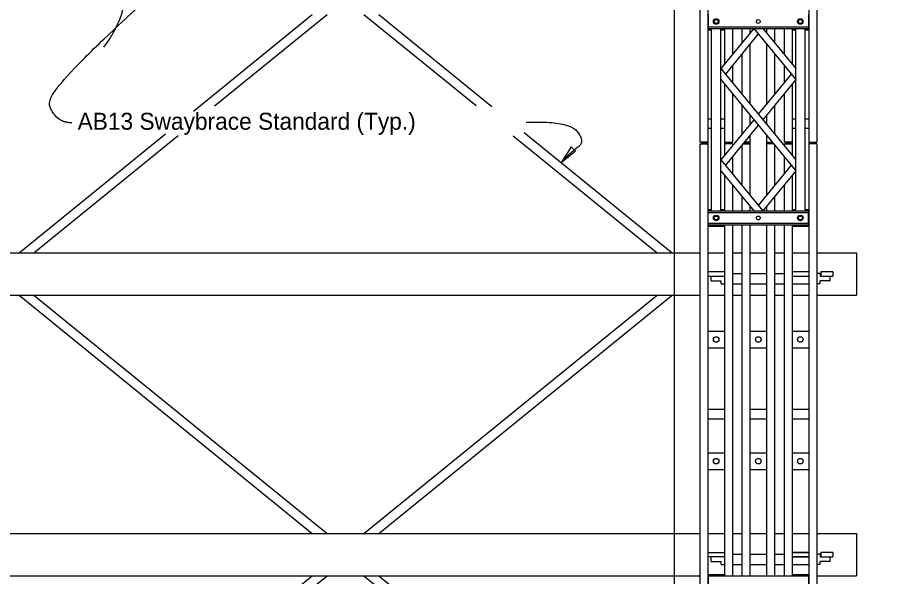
# Model space of a CAD drawing. Extents: x 10618 to 10724, y 76431 to 76484.
# Drawn here: x 10649.06 to 10664.57, y 76454.3 to 76464.26 of the extents above; entities that cross this region are included whole.
import ezdxf

# ---------------------------------------------------------------- set-up
doc = ezdxf.new("R2010")
doc.units = 0
for name, color, linetype in [('Dimension', 7, 'Continuous'), ('GroundLines', 7, 'Continuous'), ('SteelMisc', 7, 'Continuous'), ('SteelMisc_h', 7, 'Continuous'), ('TextStructures', 7, 'Continuous')]:
    doc.layers.add(name, color=color, linetype=linetype)

msp = doc.modelspace()

# ---------------------------------------------------------------- linework, layer by layer
at = {"layer": 'Dimension'}
msp.add_lwpolyline([(10658.757, 76461.681), (10659.005, 76461.878), (10658.927, 76461.949)], close=True, dxfattribs=at)
for points in [[(10650.607, 76463.726), (10650.975, 76464.246), (10650.975, 76465.012), (10650.65, 76466.059)], [(10650.033, 76462.379), (10649.734, 76462.379), (10649.531, 76463.039), (10653.036, 76466.033)], [(10658.129, 76462.389), (10658.88, 76462.418), (10659.189, 76462.04), (10658.9, 76461.84), (10658.757, 76461.681)]]:
    msp.add_open_spline(points, degree=2, dxfattribs=at)
at = {"layer": 'GroundLines'}
msp.add_arc((10662.764, 76474.227), 22, 271.4107, 319.8102, dxfattribs=at)
at = {"layer": 'SteelMisc'}
for p, q in [((10660.764, 76474.685), (10660.764, 76448.199)), ((10661.365, 76472.269), (10661.365, 76452.037)), ((10663.162, 76472.269), (10663.162, 76452.037)), ((10661.222, 76471.998), (10661.222, 76462.037)), ((10663.305, 76471.998), (10663.305, 76462.037)), ((10661.368, 76464.31), (10661.368, 76464.06)), ((10663.159, 76464.31), (10663.159, 76464.06)), ((10661.368, 76464.091), (10663.159, 76464.091)), ((10661.368, 76464.06), (10663.159, 76464.06)), ((10661.43, 76460.81), (10661.43, 76464.06)), ((10661.597, 76460.81), (10661.597, 76464.06)), ((10662.183, 76464.06), (10661.597, 76463.346)), ((10661.662, 76464.06), (10661.662, 76463.425)), ((10661.805, 76464.06), (10661.805, 76463.6)), ((10661.972, 76464.06), (10661.972, 76463.803)), ((10662.115, 76464.06), (10662.115, 76463.978)), ((10662.183, 76464.06), (10662.93, 76463.149)), ((10662.344, 76464.06), (10662.93, 76463.346)), ((10662.412, 76464.06), (10662.412, 76463.978)), ((10662.555, 76464.06), (10662.555, 76463.803)), ((10662.722, 76464.06), (10662.722, 76463.6)), ((10662.865, 76464.06), (10662.865, 76463.425)), ((10662.93, 76460.81), (10662.93, 76464.06)), ((10663.097, 76460.81), (10663.097, 76464.06)), ((10661.365, 76464.037), (10661.43, 76464.037)), ((10661.597, 76464.037), (10661.662, 76464.037)), ((10662.263, 76463.962), (10661.678, 76463.248)), ((10662.865, 76464.037), (10662.93, 76464.037)), ((10663.097, 76464.037), (10663.162, 76464.037)), ((10662.115, 76463.781), (10662.115, 76462.714)), ((10662.412, 76463.781), (10662.412, 76462.715)), ((10661.972, 76463.606), (10661.972, 76462.889)), ((10662.555, 76463.606), (10662.555, 76462.889)), ((10661.597, 76463.346), (10662.93, 76461.721)), ((10661.805, 76463.403), (10661.805, 76463.092)), ((10662.722, 76463.403), (10662.722, 76463.093)), ((10661.597, 76463.149), (10662.93, 76461.524)), ((10662.849, 76463.248), (10662.263, 76462.534)), ((10662.93, 76463.149), (10662.344, 76462.435)), ((10661.662, 76463.07), (10661.662, 76461.8)), ((10662.865, 76463.07), (10662.865, 76461.8)), ((10661.805, 76462.895), (10661.805, 76462.037)), ((10662.722, 76462.896), (10662.722, 76462.037)), ((10661.972, 76462.692), (10661.972, 76462.178)), ((10662.555, 76462.692), (10662.555, 76462.178)), ((10662.115, 76462.517), (10662.115, 76462.353)), ((10662.412, 76462.518), (10662.412, 76462.353)), ((10661.43, 76462.446), (10661.365, 76462.446)), ((10661.662, 76462.446), (10661.597, 76462.446)), ((10662.183, 76462.435), (10661.597, 76461.721)), ((10662.263, 76462.337), (10661.678, 76461.623)), ((10662.93, 76462.446), (10662.865, 76462.446)), ((10663.162, 76462.446), (10663.097, 76462.446)), ((10661.43, 76462.279), (10661.365, 76462.279)), ((10661.365, 76462.269), (10661.365, 76448.199)), ((10661.662, 76462.279), (10661.597, 76462.279)), ((10662.93, 76462.279), (10662.865, 76462.279)), ((10663.162, 76462.279), (10663.097, 76462.279)), ((10663.162, 76462.269), (10663.162, 76448.199)), ((10661.365, 76462.037), (10661.222, 76462.037)), ((10661.365, 76462.037), (10661.222, 76462.037)), ((10661.255, 76462.037), (10661.255, 76462.019)), ((10661.338, 76462.037), (10661.338, 76462.019)), ((10661.662, 76462.037), (10661.805, 76462.037)), ((10661.662, 76462.037), (10661.805, 76462.037)), ((10661.688, 76462.037), (10661.688, 76462.019)), ((10661.772, 76462.037), (10661.772, 76462.019)), ((10662.115, 76462.037), (10662.017, 76462.037)), ((10662.088, 76462.037), (10662.088, 76462.019)), ((10662.115, 76462.156), (10662.115, 76461.089)), ((10662.412, 76462.156), (10662.412, 76461.09)), ((10662.412, 76462.037), (10662.51, 76462.037)), ((10662.438, 76462.037), (10662.438, 76462.019)), ((10662.865, 76462.037), (10662.722, 76462.037)), ((10662.865, 76462.037), (10662.722, 76462.037)), ((10662.755, 76462.037), (10662.755, 76462.019)), ((10662.838, 76462.037), (10662.838, 76462.019)), ((10663.162, 76462.037), (10663.305, 76462.037)), ((10663.162, 76462.037), (10663.305, 76462.037)), ((10663.188, 76462.037), (10663.188, 76462.019)), ((10663.272, 76462.037), (10663.272, 76462.019)), ((10661.222, 76462.002), (10661.222, 76452.037)), ((10661.222, 76462.002), (10661.365, 76462.002)), ((10661.338, 76462.019), (10661.255, 76462.019)), ((10661.805, 76462.002), (10661.662, 76462.002)), ((10661.688, 76462.019), (10661.772, 76462.019)), ((10661.805, 76462.002), (10661.805, 76461.975)), ((10661.972, 76461.981), (10661.972, 76461.264)), ((10661.989, 76462.002), (10662.115, 76462.002)), ((10662.005, 76462.022), (10662.005, 76462.019)), ((10662.088, 76462.019), (10662.005, 76462.019)), ((10662.538, 76462.002), (10662.412, 76462.002)), ((10662.438, 76462.019), (10662.522, 76462.019)), ((10662.522, 76462.022), (10662.522, 76462.019)), ((10662.555, 76461.981), (10662.555, 76461.264)), ((10662.722, 76462.002), (10662.722, 76461.975)), ((10662.722, 76462.002), (10662.865, 76462.002)), ((10662.838, 76462.019), (10662.755, 76462.019)), ((10663.305, 76462.002), (10663.162, 76462.002)), ((10663.188, 76462.019), (10663.272, 76462.019)), ((10663.305, 76462.002), (10663.305, 76452.037)), ((10661.597, 76461.721), (10662.344, 76460.81)), ((10661.805, 76461.778), (10661.805, 76461.467)), ((10662.722, 76461.778), (10662.722, 76461.468)), ((10662.849, 76461.623), (10662.263, 76460.909)), ((10661.597, 76461.524), (10662.183, 76460.81)), ((10661.662, 76461.445), (10661.662, 76460.81)), ((10662.93, 76461.524), (10662.344, 76460.81)), ((10662.865, 76461.445), (10662.865, 76460.81)), ((10661.805, 76461.27), (10661.805, 76460.81)), ((10662.722, 76461.271), (10662.722, 76460.81)), ((10661.972, 76461.067), (10661.972, 76460.81)), ((10662.555, 76461.067), (10662.555, 76460.81)), ((10661.365, 76460.834), (10661.43, 76460.834)), ((10661.368, 76460.81), (10663.159, 76460.81)), ((10661.368, 76460.56), (10661.368, 76460.81)), ((10661.597, 76460.834), (10661.662, 76460.834)), ((10662.115, 76460.892), (10662.115, 76460.81)), ((10662.412, 76460.893), (10662.412, 76460.81)), ((10662.865, 76460.834), (10662.93, 76460.834)), ((10663.097, 76460.834), (10663.162, 76460.834)), ((10663.159, 76460.56), (10663.159, 76460.81)), ((10661.368, 76460.78), (10663.159, 76460.78)), ((10661.365, 76460.537), (10661.662, 76460.537)), ((10661.368, 76460.591), (10663.159, 76460.591)), ((10661.368, 76460.56), (10663.159, 76460.56)), ((10661.662, 76460.56), (10661.662, 76454.31)), ((10661.805, 76460.56), (10661.805, 76454.311)), ((10661.972, 76460.56), (10661.972, 76454.311)), ((10662.115, 76460.56), (10662.115, 76454.311)), ((10662.412, 76460.56), (10662.412, 76454.31)), ((10662.555, 76460.56), (10662.555, 76454.311)), ((10662.722, 76460.56), (10662.722, 76454.311)), ((10662.865, 76460.56), (10662.865, 76454.31)), ((10662.865, 76460.537), (10663.162, 76460.537)), ((10661.365, 76460.061), (10661.662, 76460.061)), ((10661.805, 76460.061), (10661.972, 76460.061)), ((10662.115, 76460.061), (10662.412, 76460.061)), ((10662.555, 76460.061), (10662.722, 76460.061)), ((10662.865, 76460.061), (10663.162, 76460.061)), ((10663.305, 76460.061), (10664.014, 76460.061)), ((10664.014, 76460.061), (10664.014, 76459.311)), ((10661.662, 76459.726), (10661.365, 76459.726)), ((10663.162, 76459.726), (10662.865, 76459.726)), ((10663.162, 76459.726), (10662.865, 76459.726)), ((10663.589, 76459.726), (10663.38, 76459.726)), ((10663.38, 76459.726), (10663.38, 76459.645)), ((10663.589, 76459.726), (10663.589, 76459.645)), ((10661.365, 76459.645), (10661.662, 76459.645)), ((10661.424, 76459.562), (10661.424, 76459.645)), ((10661.424, 76459.562), (10661.6, 76459.562)), ((10661.6, 76459.51), (10661.6, 76459.562)), ((10661.805, 76459.697), (10661.972, 76459.697)), ((10662.115, 76459.697), (10662.412, 76459.697)), ((10662.555, 76459.697), (10662.722, 76459.697)), ((10662.865, 76459.645), (10663.162, 76459.645)), ((10662.865, 76459.645), (10663.162, 76459.645)), ((10663.367, 76459.697), (10663.305, 76459.697)), ((10663.367, 76459.697), (10663.367, 76459.645)), ((10663.367, 76459.645), (10663.589, 76459.645)), ((10663.543, 76459.562), (10663.367, 76459.562)), ((10663.367, 76459.51), (10663.367, 76459.562)), ((10663.543, 76459.562), (10663.543, 76459.645)), ((10661.6, 76459.51), (10661.662, 76459.51)), ((10661.805, 76459.51), (10661.972, 76459.51)), ((10662.115, 76459.51), (10662.412, 76459.51)), ((10662.555, 76459.51), (10662.722, 76459.51)), ((10662.865, 76459.51), (10663.162, 76459.51)), ((10663.367, 76459.51), (10663.305, 76459.51)), ((10661.365, 76459.311), (10661.662, 76459.311)), ((10661.805, 76459.311), (10661.972, 76459.311)), ((10662.115, 76459.311), (10662.412, 76459.311)), ((10662.555, 76459.311), (10662.722, 76459.311)), ((10662.865, 76459.311), (10663.162, 76459.311)), ((10663.305, 76459.311), (10664.014, 76459.311)), ((10661.365, 76458.667), (10661.662, 76458.667)), ((10662.115, 76458.667), (10662.412, 76458.667)), ((10662.865, 76458.667), (10663.162, 76458.667)), ((10661.365, 76458.37), (10661.662, 76458.37)), ((10662.115, 76458.37), (10662.412, 76458.37)), ((10662.865, 76458.37), (10663.162, 76458.37)), ((10661.662, 76457.269), (10661.365, 76457.269)), ((10662.412, 76457.269), (10662.115, 76457.269)), ((10663.162, 76457.269), (10662.865, 76457.269)), ((10661.662, 76457.102), (10661.365, 76457.102)), ((10662.412, 76457.102), (10662.115, 76457.102)), ((10663.162, 76457.102), (10662.865, 76457.102)), ((10661.365, 76456.5), (10661.662, 76456.5)), ((10662.115, 76456.5), (10662.412, 76456.5)), ((10662.865, 76456.5), (10663.162, 76456.5)), ((10661.365, 76456.204), (10661.662, 76456.204)), ((10662.115, 76456.204), (10662.412, 76456.204)), ((10662.865, 76456.204), (10663.162, 76456.204)), ((10661.365, 76455.061), (10661.662, 76455.061)), ((10661.805, 76455.061), (10661.972, 76455.061)), ((10662.115, 76455.061), (10662.412, 76455.061)), ((10662.555, 76455.061), (10662.722, 76455.061)), ((10662.865, 76455.061), (10663.162, 76455.061)), ((10663.305, 76455.061), (10664.014, 76455.061)), ((10664.014, 76455.061), (10664.014, 76454.311)), ((10661.365, 76454.726), (10661.662, 76454.726)), ((10661.662, 76454.645), (10661.365, 76454.645)), ((10661.424, 76454.562), (10661.424, 76454.645)), ((10661.805, 76454.697), (10661.972, 76454.697)), ((10662.115, 76454.697), (10662.412, 76454.697)), ((10662.555, 76454.697), (10662.722, 76454.697)), ((10662.865, 76454.726), (10663.162, 76454.726)), ((10663.162, 76454.726), (10662.865, 76454.726)), ((10663.162, 76454.645), (10662.865, 76454.645)), ((10662.865, 76454.645), (10663.162, 76454.645)), ((10663.367, 76454.697), (10663.305, 76454.697)), ((10663.367, 76454.697), (10663.367, 76454.645)), ((10663.367, 76454.645), (10663.589, 76454.645)), ((10663.589, 76454.726), (10663.38, 76454.726)), ((10663.38, 76454.726), (10663.38, 76454.645)), ((10663.543, 76454.562), (10663.543, 76454.645)), ((10663.589, 76454.726), (10663.589, 76454.645)), ((10661.424, 76454.562), (10661.6, 76454.562)), ((10661.6, 76454.51), (10661.6, 76454.562)), ((10661.6, 76454.51), (10661.662, 76454.51)), ((10661.805, 76454.51), (10661.972, 76454.51)), ((10662.115, 76454.51), (10662.412, 76454.51)), ((10662.555, 76454.51), (10662.722, 76454.51)), ((10662.865, 76454.51), (10663.162, 76454.51)), ((10663.367, 76454.51), (10663.305, 76454.51)), ((10663.543, 76454.562), (10663.367, 76454.562)), ((10663.367, 76454.51), (10663.367, 76454.562)), ((10661.365, 76454.334), (10661.662, 76454.334)), ((10661.365, 76454.311), (10661.662, 76454.311)), ((10661.368, 76454.31), (10663.159, 76454.31)), ((10661.368, 76454.31), (10661.368, 76454.06)), ((10661.805, 76454.311), (10662.722, 76454.311)), ((10662.865, 76454.334), (10663.162, 76454.334)), ((10662.865, 76454.311), (10663.162, 76454.311)), ((10663.159, 76454.31), (10663.159, 76454.06)), ((10663.305, 76454.311), (10664.014, 76454.311))]:
    msp.add_line(p, q, dxfattribs=at)
for centre, radius in [((10661.513, 76464.185), 0.0495), ((10661.513, 76464.185), 0.0339), ((10662.263, 76464.185), 0.0339), ((10663.013, 76464.185), 0.0495), ((10663.013, 76464.185), 0.0339), ((10661.513, 76460.685), 0.0495), ((10661.513, 76460.685), 0.0339), ((10662.263, 76460.685), 0.0339), ((10663.013, 76460.685), 0.0495), ((10663.013, 76460.685), 0.0339), ((10661.513, 76458.519), 0.0495), ((10662.263, 76458.519), 0.0495), ((10663.013, 76458.519), 0.0495), ((10661.513, 76456.352), 0.0495), ((10662.263, 76456.352), 0.0495), ((10663.013, 76456.352), 0.0495)]:
    msp.add_circle(centre, radius, dxfattribs=at)
at = {"layer": 'SteelMisc_h'}
for p, q in [((10652.199, 76462.588), (10654.317, 76464.311)), ((10652.578, 76462.681), (10654.581, 76464.311)), ((10655.239, 76464.311), (10657.235, 76462.687)), ((10655.503, 76464.311), (10657.517, 76462.672)), ((10649.093, 76460.061), (10651.704, 76462.185)), ((10658.092, 76462.204), (10660.727, 76460.061)), ((10649.357, 76460.061), (10651.926, 76462.151)), ((10657.896, 76462.149), (10660.463, 76460.061)), ((10636.305, 76460.061), (10661.222, 76460.061)), ((10636.305, 76459.311), (10661.222, 76459.311)), ((10649.093, 76459.311), (10654.317, 76455.061)), ((10649.357, 76459.311), (10654.581, 76455.061)), ((10655.239, 76455.061), (10660.463, 76459.311)), ((10655.503, 76455.061), (10660.727, 76459.311)), ((10636.305, 76455.061), (10661.222, 76455.061)), ((10636.305, 76454.311), (10661.222, 76454.311)), ((10651.912, 76452.354), (10654.317, 76454.311)), ((10652.096, 76452.289), (10654.581, 76454.311)), ((10655.239, 76454.311), (10660.463, 76450.061)), ((10655.503, 76454.311), (10660.727, 76450.061))]:
    msp.add_line(p, q, dxfattribs=at)

# ---------------------------------------------------------------- texts
at = {"layer": 'TextStructures'}
msp.add_text('AB13 Swaybrace Standard (Typ.)', height=0.3024, dxfattribs=at).set_placement((10650.137, 76462.256))

doc.saveas('drawing.dxf')
